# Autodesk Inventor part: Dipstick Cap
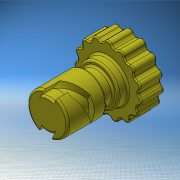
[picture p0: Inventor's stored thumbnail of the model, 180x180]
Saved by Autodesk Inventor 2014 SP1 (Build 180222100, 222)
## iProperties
Created: 2014-12
Part Number: Dipstick Cap
Material: Generic
Document SubType Name: Modeling
Designer: isaak
Density: 1 g/cm^3
Appearance: Canary
Author: isaak
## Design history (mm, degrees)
sketch "Sketch1"
  geometry: C1 r 8.509 at (0, 0); 1 further point
  constraints: 1 centre point, 1 coincident
  dimensions: "d0" = 17.018 diameter of C1
extrude "Extrusion1" new body sketch "Sketch1" distance "d1" = 25.4; taper "d2" = 0 deg
sketch "Sketch2"
  geometry: L1 (-2.803, 5.698)-(-1.559, 8.365); L2 (2.803, 5.698)-(3.715, 7.655); L3 (2.803, -5.698)-(1.559, -8.365); L4 (-2.803, -5.698)-(-3.715, -7.655); L5 (-2.803, -5.698)-(2.803, -5.698); L6 (-2.803, 5.698)-(2.803, 5.698); A1 r 8.509 centre (0, 0) between (-1.559, 8.365) and (3.715, 7.655) reference; A2 r 6.35 centre (0, 0) between (-2.803, 5.698) and (2.803, 5.698)
  constraints: 12 end point, 8 point on circle, 3 parallel, 2 horizontal, 1 centre point, 1 coincident
  dimensions: "d3" = 12.7 diameter of A2; "d4" = 5.08 distance between parallel lines of L1 L2; "d5" = 5.08 distance between parallel lines of L3 L4 (= d4); "d6" = 65 deg angle of L5 L3
extrude "Extrusion2" cut sketch "Sketch2" distance "d7" = 5.08; taper "d8" = 0 deg
workplane "Work Plane1"
sketch "Sketch3"
  geometry: L1 (3.715, 7.655)-(2.803, 5.698) reference; L2 (-2.803, 5.698)-(-1.559, 8.365) reference; L3 (-3.715, -7.655)-(-2.803, -5.698) reference; L4 (2.803, -5.698)-(1.559, -8.365) reference; L5 (2.794, 5.702)-(5.159, 6.766); L6 (-5.159, 6.766)-(-2.794, 5.702); L7 (0, 0)-(2.181, 0); L8 (0, 6.35)-(0, 0); A1 r 6.35 centre (0, 0) between (2.803, 5.698) and (-2.803, 5.698) reference; A2 r 8.509 centre (0, 0) between (3.715, 7.655) and (-1.559, 8.365) reference; A3 r 6.35 centre (0, 0) between (-2.803, -5.698) and (2.803, -5.698) reference; A4 r 8.509 centre (0, 0) between (-3.715, -7.655) and (1.559, -8.365) reference; A5 r 8.509 centre (0, 0) between (5.159, 6.766) and (-5.159, 6.766); A6 r 6.35 centre (0, 0) between (2.794, 5.702) and (-2.794, 5.702); 1 further point
  constraints: 8 end point, 5 point on circle, 3 concentric, 2 centre point, 2 coincident, 1 horizontal, 1 perpendicular
  dimensions: "d18" = 131.557 deg angle of L5 L6 (derived); "d21" = 10.31875 distance of L6.start L5.end; "d22" = 5.588 distance of L5.start L6.end; "d23" = 65.7787 deg angle of L5 L8 (= 0.5 x d18); "d24" = 65.7787 deg angle of L6 L8 (derived)
sketch "3D Sketch1"
sweep "Sweep1" sketch "Sketch3", "3D Sketch1" dims "d17" = 0
sketch "Sketch4"
  geometry: L1 (0, 0)-(-0.04, 2.935) reference; L2 (0, 0)-(2.588, 0) reference; A1 r 8.509 centre (-4.893, -4.054) between (2.588, 0) and (-0.04, 2.935) reference
extrude "Extrusion3" join sketch "Sketch4" stored distance "d25" = 5.08; taper "d26" = 0 deg; dims "d13" = 25.4
workplane "Work Plane2"
sketch "Sketch5"
  geometry: C1 r 8.509 at (0, 0) reference; C2 r 6.35 at (0, 0); 1 further point
  constraints: 1 centre point, 1 coincident
  dimensions: "d28" = 12.7 diameter of C2
extrude "Extrusion4" cut sketch "Sketch5" distance "d29" = 4.7625; taper "d30" = 0 deg
sketch "Sketch6"
  geometry: C1 r 8.509 at (0, 0) reference; C2 r 12.7 at (0, 0)
  constraints: 1 centre point, 1 coincident
  dimensions: "d31" = 25.4 diameter of C2
extrude "Extrusion5" join sketch "Sketch6" distance "d32" = 9.525; taper "d33" = 0 deg
sketch "Sketch7"
  geometry: A1 r 12.7 centre (0, 0) between (-2.95, 12.353) and (2.95, 12.353) reference; A2 r 2.54 centre (-3.539, 14.823) between (-2.95, 12.353) and (-1.361, 13.517); A3 r 1.587 centre (0, 12.7) between (1.361, 13.517) and (-1.361, 13.517); A4 r 2.54 centre (3.539, 14.823) between (1.361, 13.517) and (2.95, 12.353)
  constraints: 9 point on circle, 4 tangent, 3 centre point, 1 equal radius, 1 vertical alignment
  dimensions: "d34" = 1.5875 radius of A3; "d35" = 2.54 radius of A2
extrude "Extrusion6" join sketch "Sketch7" distance "d36" = 9.525; taper "d37" = 0 deg
pattern_circular "Circular Pattern1" dims angle "d39" = 360 deg
fillet "Fillet1" dims "d41" = 0.508
pattern_circular "Circular Pattern2" dims angle "d43" = 180 deg
fillet "Fillet2" dims "d45" = 0.79375, "d46" = 0.79375
sketch "Sketch9"
  geometry: L1 (-12.7, 7.938)-(12.7, 7.938); L2 (12.7, 7.938)-(12.7, -7.938); L3 (12.7, -7.938)-(-12.7, -7.938); L4 (-12.7, -7.938)-(-12.7, 7.938); 3 further points
  constraints: 2 midpoint, 1 horizontal, 1 horizontal alignment, 1 vertical alignment, 2 other
  dimensions: "d50" = 25.4 distance of L1.start L1.end; "d51" = 15.875 distance of L1.end L2.end
emboss "Emboss2" sketch "Sketch9" dims "d52" = 0.79375, "d53" = 0
sketch "Sketch8"
  geometry: C1 r 7.938 at (0, 0); 1 further point
  constraints: 1 centre point, 1 coincident, 1 other
  dimensions: "d47" = 15.875 diameter of C1
emboss "Emboss1" sketch "Sketch8" dims "d48" = 0.79375, "d49" = 0
body "Solid1"
node "Projected Loop1"
node "Projected Loop2"
node "Helical Curve1" dims "d13" = 25.4, "d14" = 2.5, "d15" = 12.7, "d16" = 0
node "Projected Loop3"
other parameters: "d9" = -4.7625, "d27" = -16.51
